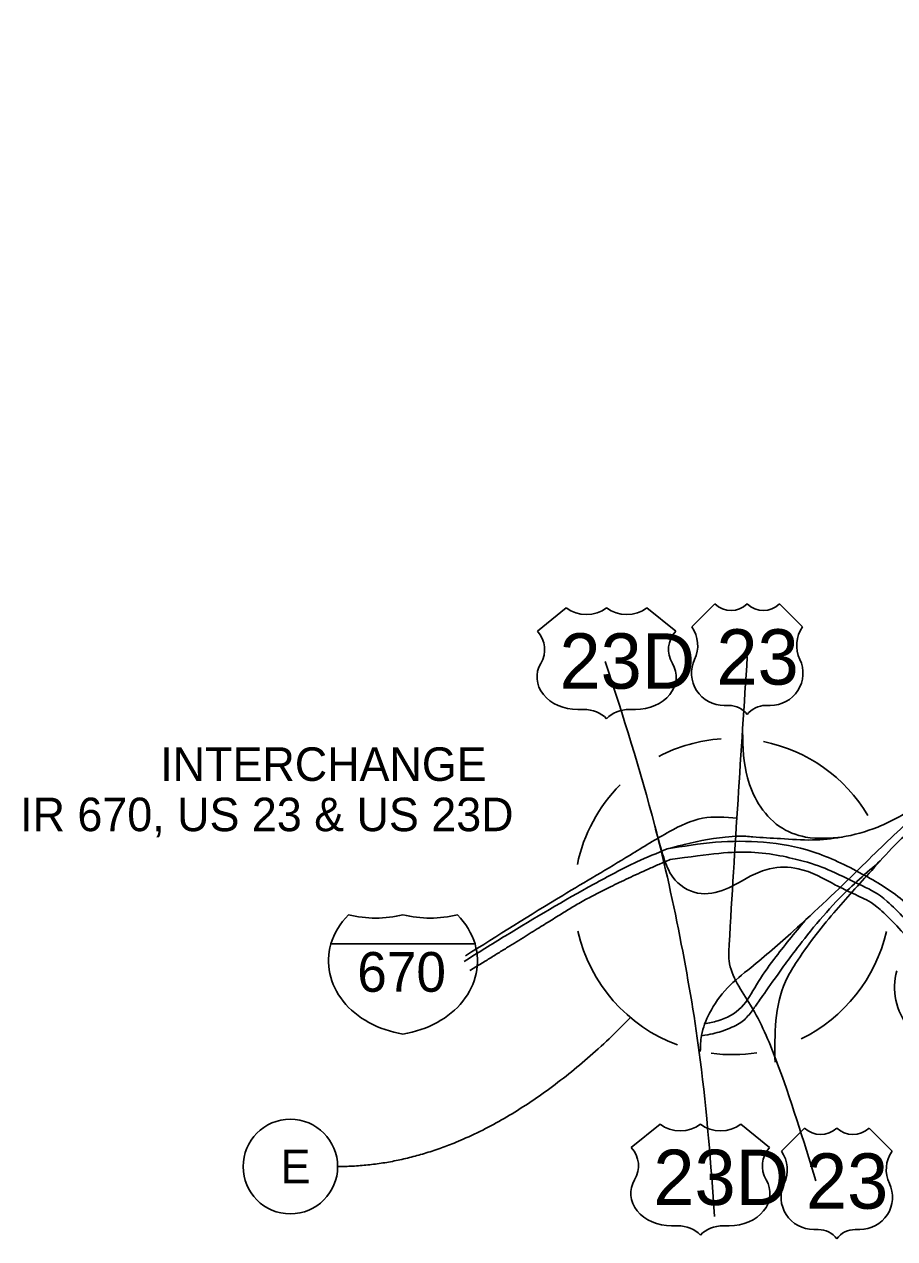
# Model space of a CAD drawing. Extents: x -13 to 322, y -402 to 112.
# Drawn here: x -0.78 to 2.189, y 102.16 to 106.302 of the extents above; entities that cross this region are included whole.
import ezdxf

# ---------------------------------------------------------------- set-up
doc = ezdxf.new("R2010")
doc.units = 0
for name, color, linetype in [('GM_X_Interstate_Shield', 7, 'Continuous'), ('GM_X_US_Shield', 7, 'Continuous'), ('SH_Data', 7, 'Continuous'), ('SH_Text', 7, 'Continuous')]:
    doc.layers.add(name, color=color, linetype=linetype)

msp = doc.modelspace()

# ---------------------------------------------------------------- linework, layer by layer
at = {"layer": 'GM_X_Interstate_Shield'}
msp.add_line((0.7575, 103.1655), (0.2659, 103.1655), dxfattribs=at)
msp.add_line((0.7575, 103.1655), (0.2659, 103.1655), dxfattribs=at)
for centre, start_param, end_param in [((0.5753, 103.1074), 2.47259, 2.911027), ((0.4188, 103.5082), 4.415841, 5.008937), ((0.6046, 103.5082), 4.415841, 5.008937), ((0.4481, 103.1074), 0.230566, 0.669003), ((0.5753, 103.1074), 2.911027, 4.511031), ((0.4481, 103.1074), 4.913747, 6.513751), ((2.5061, 103.0164), 2.911027, 4.511031)]:
    msp.add_ellipse(centre, major_axis=(0.3178, 0), ratio=0.8, start_param=start_param, end_param=end_param, dxfattribs=at)
at = {"layer": 'GM_X_US_Shield'}
for p, q in [((1.0685, 104.3115), (0.9702, 104.2329)), ((1.4421, 104.2329), (1.3438, 104.3115)), ((1.5759, 104.3253), (1.4972, 104.2467)), ((1.8747, 104.2467), (1.7961, 104.3253)), ((1.1079, 103.9655), (1.1275, 103.9655)), ((1.2848, 103.9655), (1.3045, 103.9655)), ((1.6073, 103.9793), (1.6231, 103.9793)), ((1.7489, 103.9793), (1.7646, 103.9793)), ((1.3887, 102.5505), (1.2904, 102.4718)), ((1.7622, 102.4718), (1.6639, 102.5505)), ((1.8813, 102.5378), (1.8026, 102.4592)), ((2.1801, 102.4592), (2.1015, 102.5378)), ((1.428, 102.2044), (1.4477, 102.2044)), ((1.6049, 102.2044), (1.6246, 102.2044)), ((1.9127, 102.1918), (1.9285, 102.1918)), ((2.0543, 102.1918), (2.07, 102.1918))]:
    msp.add_line(p, q, dxfattribs=at)
for centre, radius, start, end in [((1.6309, 104.3815), 0.0786, 225.573, 314.427), ((1.741, 104.3815), 0.0786, 225.573, 314.427), ((1.407, 104.1835), 0.1101, 334.5471, 35.0009), ((1.9649, 104.1835), 0.1101, 144.9991, 205.4529), ((1.6061, 104.0894), 0.1101, 154.8319, 270.6383), ((1.7659, 104.0894), 0.1101, 269.3617, 25.1681), ((1.6231, 103.9007), 0.0786, 36.8699, 90), ((1.7489, 103.9007), 0.0786, 90, 143.1301), ((1.9363, 102.594), 0.0786, 225.573, 314.427), ((2.0464, 102.594), 0.0786, 225.573, 314.427), ((1.7124, 102.396), 0.1101, 334.5471, 35.0009), ((2.2703, 102.396), 0.1101, 144.9991, 205.4529), ((1.9115, 102.3019), 0.1101, 154.8319, 270.6383), ((2.0713, 102.3019), 0.1101, 269.3617, 25.1681), ((1.9285, 102.1131), 0.0786, 36.8699, 90), ((2.0543, 102.1131), 0.0786, 90, 143.1301)]:
    msp.add_arc(centre, radius, start, end, dxfattribs=at)
for centre, major_axis, start_param, end_param in [((1.1374, 104.3677), (-0.0983, 0), 0.795399, 2.346194), ((1.275, 104.3677), (-0.0983, 0), 0.795399, 2.346194), ((0.8575, 104.1697), (0.1376, 0), 5.838949, 6.894067), ((1.5548, 104.1697), (-0.1376, 0), 5.672304, 6.727422), ((1.1063, 104.0756), (0.1376, 0), 2.702327, 4.723529), ((1.306, 104.0756), (-0.1376, 0), 1.559657, 3.580859), ((1.1275, 103.8868), (-0.0983, 0), 3.785094, 4.712389), ((1.2848, 103.8868), (-0.0983, 0), 4.712389, 5.639684), ((1.4575, 102.6067), (-0.0983, 0), 0.795399, 2.346194), ((1.5951, 102.6067), (-0.0983, 0), 0.795399, 2.346194), ((1.1776, 102.4087), (0.1376, 0), 5.838949, 6.894067), ((1.875, 102.4087), (-0.1376, 0), 5.672304, 6.727422), ((1.4265, 102.3145), (0.1376, 0), 2.702327, 4.723529), ((1.6261, 102.3145), (-0.1376, 0), 1.559657, 3.580859), ((1.4477, 102.1258), (-0.0983, 0), 3.785094, 4.712389), ((1.6049, 102.1258), (-0.0983, 0), 4.712389, 5.639684)]:
    msp.add_ellipse(centre, major_axis=major_axis, ratio=0.8, start_param=start_param, end_param=end_param, dxfattribs=at)
at = {"layer": 'SH_Data'}
msp.add_circle((0.1276, 102.4065), 0.1612, dxfattribs=at)
for start, end in [(93.9989, 117.6869), (30.8246, 78.577), (135.0515, 168.2637), (192.7151, 249.7617), (295.8597, 347.2359), (262.4144, 279.0213)]:
    msp.add_arc((1.6346, 103.3274), 0.5393, start, end, dxfattribs=at)
for points in [[(3.7092, 104.6637), (3.5843, 105.5418), (3.5502, 105.8224), (3.5419, 106.018), (3.5884, 106.6724), (3.6232, 107.0317), (3.6255, 107.0682), (3.6713, 107.6752), (3.713, 108.1683), (3.7189, 108.3717), (3.7325, 109.1742), (3.7325, 109.2177), (3.7156, 109.4217), (3.6709, 109.6129), (3.5578, 109.8519), (3.4048, 110.0687), (3.2534, 110.2041), (2.9985, 110.3714), (2.7278, 110.5625), (2.5969, 110.6787), (2.4431, 110.8702), (2.3082, 111.1041), (2.2413, 111.2745), (2.1732, 111.5886), (2.143, 111.8754)], [(1.2019, 104.1293), (1.3708, 103.5689), (1.4611, 103.1652), (1.5257, 102.7704), (1.5748, 102.2358)], [(1.6861, 104.1445), (1.6243, 103.1633), (1.6243, 103.1081), (1.6974, 102.9569), (1.7836, 102.7716), (1.92, 102.3575)], [(3.0507, 104.0903), (2.8452, 103.9921), (2.6446, 103.85), (2.3242, 103.6202), (2.1884, 103.5012), (2.1105, 103.4165), (1.9812, 103.2718), (1.8511, 103.0988), (1.8166, 103.0375), (1.7808, 102.762)], [(2.0108, 103.5304), (1.8851, 103.5304), (1.7956, 103.5667), (1.7249, 103.6434), (1.6865, 103.7321), (1.67, 103.8892)], [(2.5058, 103.7943), (2.2415, 103.5874), (2.069, 103.4227), (1.8432, 103.2095), (1.6978, 103.0844), (1.6183, 103.0156), (1.5573, 102.9294), (1.5301, 102.8538), (1.5259, 102.7991)], [(2.3934, 103.7171), (2.2735, 103.6404), (2.1311, 103.5644), (2.0072, 103.5298), (1.909, 103.5202), (1.7993, 103.5249), (1.7051, 103.5307), (1.6575, 103.5338), (1.6111, 103.5301), (1.571, 103.5252), (1.4128, 103.4896)], [(1.6515, 103.5944), (1.5334, 103.5944), (1.4213, 103.5491), (1.2864, 103.4689), (1.0568, 103.3313), (0.725, 103.1253)], [(1.9871, 103.3665), (1.8602, 103.4221), (1.7625, 103.4221), (1.6985, 103.3974), (1.6121, 103.3525), (1.5167, 103.339), (1.4325, 103.3929), (1.4011, 103.4602), (1.3735, 103.5571)], [(1.4128, 103.4896), (1.5781, 103.5123), (1.7417, 103.5123), (1.9092, 103.4801), (2.078, 103.4041), (2.2159, 103.3152), (2.4001, 103.1), (2.448, 103.0403), (2.5717, 102.9032), (2.7188, 102.7929), (2.8622, 102.7562)], [(1.4128, 103.4896), (1.3092, 103.4452), (1.1625, 103.3696), (0.8617, 103.1937), (0.7205, 103.1062)], [(1.912, 103.2224), (2.0011, 103.322), (2.1398, 103.4487)], [(1.8831, 103.2456), (1.777, 103.1131), (1.7172, 103.0258), (1.6659, 102.9498), (1.5852, 102.9033), (1.5404, 102.8934)]]:
    msp.add_spline(points, degree=3, dxfattribs=at)
for points, degree in [([(3.746, 104.6689), (3.7, 104.9919), (3.6496, 105.3161), (3.5602, 105.9597), (3.5923, 106.2792), (3.6806, 107.2532), (3.7425, 107.9064), (3.7649, 108.7199), (3.7698, 108.883), (3.7702, 109.2113), (3.7707, 109.3812), (3.6831, 109.7044), (3.6074, 109.8565), (3.4132, 110.1323), (3.2743, 110.2359), (3.0026, 110.4169), (2.862, 110.5067), (2.6127, 110.6968), (2.512, 110.8246), (2.2567, 111.2315), (2.2141, 111.5548), (2.1799, 111.8793)], 3), ([(1.4228, 103.4535), (1.5642, 103.4729), (1.7012, 103.4907), (1.8983, 103.4448), (1.9636, 103.4199), (2.0899, 103.3575), (2.1491, 103.3319), (2.2958, 103.1766), (2.3805, 103.0627), (2.5242, 102.8979), (2.5735, 102.8402), (2.7038, 102.7498), (2.7881, 102.7369), (2.853, 102.7203)], 3), ([(1.4228, 103.4535), (1.1864, 103.3516), (0.9626, 103.2125), (0.74, 103.0746)], 2), ([(1.9871, 103.3665), (1.9948, 103.363), (2.0025, 103.3593), (2.0745, 103.3237), (2.1231, 103.3053), (2.2668, 103.1533), (2.3529, 103.0378), (2.4961, 102.8737), (2.5427, 102.8163), (2.6922, 102.7127), (2.7819, 102.7001), (2.8438, 102.6843)], 3), ([(1.912, 103.2224), (1.8534, 103.1491), (1.7981, 103.0732), (1.7298, 102.9765), (1.7162, 102.957), (1.689, 102.918), (1.6589, 102.8912), (1.5949, 102.8646), (1.5615, 102.8578), (1.5299, 102.8519)], 3), ([(1.2881, 102.9143), (0.7885, 102.4065), (0.2888, 102.4065)], 2)]:
    msp.add_open_spline(points, degree=degree, dxfattribs=at)

# ---------------------------------------------------------------- texts
at = {"layer": 'GM_X_Interstate_Shield'}
msp.add_text('670', height=0.13558, dxfattribs=at).set_placement((0.3558, 103.0024))
at = {"layer": 'GM_X_US_Shield'}
for s, p in [('23D', (1.0455, 104.0363)), ('23', (1.5809, 104.0501)), ('23D', (1.3657, 102.2752)), ('23', (1.8863, 102.2626))]:
    msp.add_text(s, height=0.18875, dxfattribs=at).set_placement(p)
at = {"layer": 'SH_Data'}
msp.add_text('E', height=0.1144, dxfattribs=at).set_placement((0.0943, 102.3493))
at = {"layer": 'SH_Text'}
for s, p in [('INTERCHANGE', (-0.3161, 103.7218)), ('IR 670, US 23 & US 23D', (-0.7942, 103.5502))]:
    msp.add_text(s, height=0.114366, dxfattribs=at).set_placement(p)

doc.saveas('drawing.dxf')
